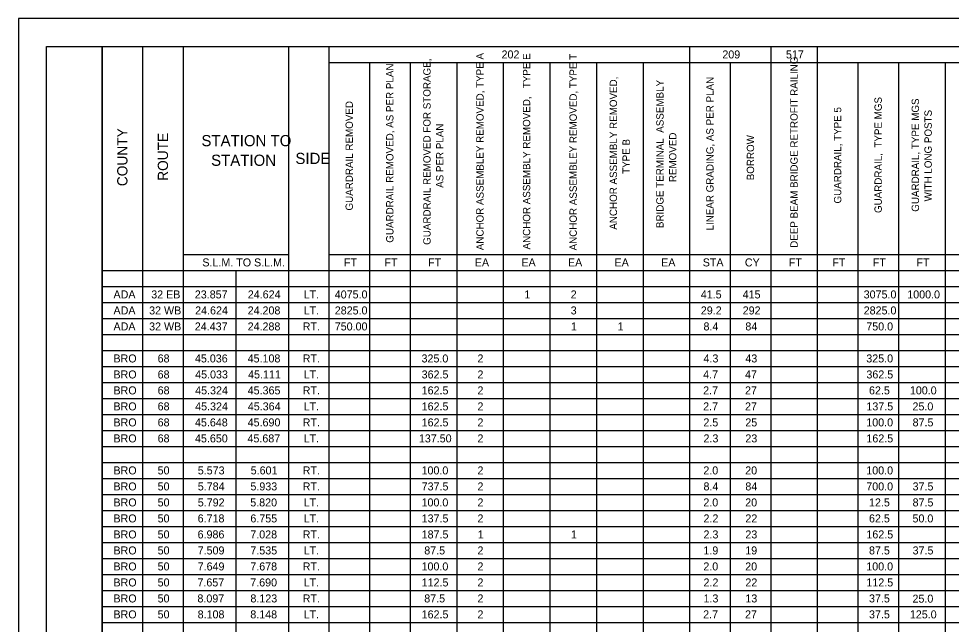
# Model space of a CAD drawing. Extents: x 0 to 34, y 0 to 22.
# Drawn here: x 0 to 16.78, y 11.1 to 22 of the extents above; entities that cross this region are included whole.
import ezdxf

# ---------------------------------------------------------------- set-up
doc = ezdxf.new("R2010")
doc.units = 0
for name, color, linetype in [('Default', 7, 'Continuous'), ('SH_Border', 7, 'Continuous'), ('SH_Cut_Line', 7, 'Continuous')]:
    doc.layers.add(name, color=color, linetype=linetype)

msp = doc.modelspace()

# ---------------------------------------------------------------- linework, layer by layer
at = {"layer": 'Default'}
for p, q in [((1.5, 21.5), (24.449, 21.5)), ((1.5, 21.5), (1.5, 0.498)), ((2.229, 21.5), (2.229, 1.345)), ((2.959, 21.5), (2.959, 1.345)), ((4.852, 21.5), (4.852, 1.345)), ((5.582, 21.5), (5.582, 0.498)), ((12.069, 21.5), (12.069, 0.498)), ((13.528, 21.5), (13.528, 0.498)), ((14.366, 21.5), (14.366, 0.498)), ((5.582, 21.212), (24.428, 21.212)), ((6.311, 21.212), (6.311, 0.498)), ((7.041, 21.212), (7.041, 0.498)), ((7.879, 21.212), (7.879, 0.498)), ((8.717, 21.212), (8.717, 0.498)), ((9.555, 21.212), (9.555, 0.498)), ((10.393, 21.212), (10.393, 0.498)), ((11.231, 21.212), (11.231, 0.498)), ((12.799, 21.212), (12.799, 0.498)), ((15.096, 21.212), (15.096, 0.498)), ((15.825, 21.212), (15.825, 0.498)), ((16.663, 21.212), (16.663, 0.498)), ((2.959, 17.757), (4.852, 17.757)), ((5.582, 17.757), (24.428, 17.757)), ((1.5, 17.469), (24.428, 17.469)), ((3.906, 17.469), (3.906, 1.345)), ((1.5, 17.181), (24.428, 17.181)), ((1.5, 16.893), (24.428, 16.893)), ((1.5, 16.605), (24.428, 16.605)), ((1.5, 16.317), (24.428, 16.317)), ((1.5, 16.029), (24.428, 16.029)), ((1.5, 15.741), (24.428, 15.741)), ((1.5, 15.453), (24.428, 15.453)), ((1.5, 15.166), (24.428, 15.166)), ((1.5, 14.878), (24.428, 14.878)), ((1.5, 14.59), (24.428, 14.59)), ((1.5, 14.302), (24.428, 14.302)), ((1.5, 14.014), (24.428, 14.014)), ((1.5, 13.726), (24.428, 13.726)), ((1.5, 13.438), (24.428, 13.438)), ((1.5, 13.15), (24.428, 13.15)), ((1.5, 12.862), (24.428, 12.862)), ((1.5, 12.574), (24.428, 12.574)), ((1.5, 12.286), (24.428, 12.286)), ((1.5, 11.998), (24.428, 11.998)), ((1.5, 11.71), (24.428, 11.71)), ((1.5, 11.422), (24.428, 11.422)), ((1.5, 11.135), (24.428, 11.135))]:
    msp.add_line(p, q, dxfattribs=at)
at = {"layer": 'SH_Border'}
for points in [[(0.5, 21.5), (1.5, 21.5), (1.5, 0.5), (0.5, 0.5)], [(1.5, 21.5), (33.5, 21.5), (33.5, 0.5), (1.5, 0.5)]]:
    msp.add_lwpolyline(points, close=True, dxfattribs=at)
at = {"layer": 'SH_Cut_Line'}
msp.add_lwpolyline([(0, 0), (34, 0), (34, 22), (0, 22)], close=True, dxfattribs=at)

# ---------------------------------------------------------------- texts
at = {"layer": 'Default'}
for s, height, p in [('ANCHOR ASSEMBLEY REMOVED, TYPE A', 0.13192, (8.364, 17.833)), ('ANCHOR ASSEMBLY REMOVED,   TYPE E', 0.13192, (9.202, 17.846)), ('ANCHOR ASSEMBLEY REMOVED, TYPE T', 0.13192, (10.04, 17.829)), ('GUARDRAIL REMOVED, AS PER PLAN', 0.13192, (6.742, 17.967)), ('GUARDRAIL REMOVED FOR STORAGE,  ', 0.13192, (7.41, 17.929)), ('DEEP BEAM BRIDGE RETROFIT RAILING', 0.13192, (14.013, 17.876)), ('ANCHOR ASSEMBLY REMOVED,          ', 0.13192, (10.763, 18.202)), ('BRIDGE TERMINAL  ASSEMBLY ', 0.13192, (11.601, 18.231)), ('LINEAR GRADING, AS PER PLAN', 0.13192, (12.5, 18.188)), ('GUARDRAIL REMOVED', 0.13192, (6.012, 18.547)), ('GUARDRAIL,  TYPE MGS', 0.13192, (15.526, 18.502)), ('GUARDRAIL, TYPE MGS ', 0.13192, (16.195, 18.525)), ('GUARDRAIL, TYPE 5', 0.13192, (14.797, 18.673)), ('WITH LONG POSTS', 0.13192, (16.425, 18.711)), ('COUNTY', 0.1847, (1.957, 18.985)), ('AS PER PLAN', 0.13192, (7.641, 18.955)), ('ROUTE', 0.1847, (2.687, 19.081)), ('TYPE B', 0.1319, (10.993, 19.207)), ('REMOVED', 0.1319, (11.831, 19.058)), ('BORROW', 0.1319, (13.229, 19.091))]:
    msp.add_text(s, height=height, rotation=90, dxfattribs=at).set_placement(p)
for s, height, p in [('202', 0.144, (8.686, 21.284)), ('209', 0.144, (12.658, 21.284)), ('517', 0.144, (13.802, 21.284)), ('STATION TO ', 0.20155, (3.288, 19.704)), ('STATION', 0.2016, (3.462, 19.351)), ('SIDE', 0.2016, (4.978, 19.384)), ('S.L.M. TO S.L.M.', 0.14396, (3.304, 17.541)), ('FT', 0.144, (5.851, 17.541)), ('FT', 0.144, (6.581, 17.541)), ('FT', 0.144, (7.365, 17.541)), ('EA', 0.144, (8.205, 17.541)), ('EA', 0.144, (9.043, 17.541)), ('EA', 0.144, (9.881, 17.541)), ('EA', 0.144, (10.719, 17.541)), ('EA', 0.144, (11.557, 17.541)), ('STA', 0.144, (12.305, 17.541)), ('CY', 0.144, (13.063, 17.541)), ('FT', 0.144, (13.852, 17.541)), ('FT', 0.144, (14.636, 17.541)), ('FT', 0.144, (15.365, 17.541)), ('FT', 0.144, (16.149, 17.541)), ('ADA', 0.144, (1.706, 16.965)), ('32 EB', 0.144, (2.385, 16.965)), ('23.857', 0.144, (3.169, 16.965)), ('24.624', 0.144, (4.122, 16.965)), ('LT.', 0.144, (5.126, 16.965)), ('4075.0', 0.144, (5.686, 16.965)), ('1', 0.144, (9.097, 16.965)), ('2', 0.144, (9.93, 16.965)), ('41.5', 0.144, (12.27, 16.965)), ('415', 0.144, (13.023, 16.965)), ('3075.0', 0.144, (15.2, 16.965)), ('1000.0', 0.144, (15.984, 16.965)), ('ADA', 0.144, (1.706, 16.677)), ('32 WB', 0.144, (2.347, 16.677)), ('24.624', 0.144, (3.175, 16.677)), ('24.208', 0.144, (4.119, 16.677)), ('LT.', 0.144, (5.126, 16.677)), ('2825.0', 0.144, (5.686, 16.677)), ('3', 0.144, (9.93, 16.677)), ('29.2', 0.144, (12.271, 16.677)), ('292', 0.144, (13.024, 16.677)), ('2825.0', 0.144, (15.2, 16.677)), ('ADA', 0.144, (1.706, 16.389)), ('32 WB', 0.144, (2.347, 16.389)), ('24.437', 0.144, (3.169, 16.389)), ('24.288', 0.144, (4.119, 16.389)), ('RT.', 0.144, (5.109, 16.389)), ('750.00', 0.144, (5.686, 16.389)), ('1', 0.144, (9.935, 16.389)), ('1', 0.144, (10.773, 16.389)), ('8.4', 0.144, (12.319, 16.389)), ('84', 0.144, (13.072, 16.389)), ('750.0', 0.144, (15.247, 16.389)), ('BRO', 0.144, (1.705, 15.813)), ('68', 0.144, (2.5, 15.813)), ('45.036', 0.144, (3.171, 15.813)), ('45.108', 0.144, (4.119, 15.813)), ('RT.', 0.144, (5.109, 15.813)), ('325.0', 0.144, (7.247, 15.813)), ('2', 0.144, (8.253, 15.813)), ('4.3', 0.144, (12.319, 15.813)), ('43', 0.144, (13.072, 15.813)), ('325.0', 0.144, (15.247, 15.813)), ('BRO', 0.144, (1.705, 15.525)), ('68', 0.144, (2.5, 15.525)), ('45.033', 0.144, (3.175, 15.525)), ('45.111', 0.144, (4.127, 15.525)), ('LT.', 0.144, (5.126, 15.525)), ('362.5', 0.144, (7.249, 15.525)), ('2', 0.144, (8.253, 15.525)), ('4.7', 0.144, (12.313, 15.525)), ('47', 0.144, (13.066, 15.525)), ('362.5', 0.144, (15.249, 15.525)), ('BRO', 0.144, (1.705, 15.238)), ('68', 0.144, (2.5, 15.238)), ('45.324', 0.144, (3.175, 15.238)), ('45.365', 0.144, (4.12, 15.238)), ('RT.', 0.144, (5.109, 15.238)), ('162.5', 0.144, (7.249, 15.238)), ('2', 0.144, (8.253, 15.238)), ('2.7', 0.144, (12.313, 15.238)), ('27', 0.144, (13.066, 15.238)), ('62.5', 0.144, (15.296, 15.238)), ('100.0', 0.144, (16.031, 15.238)), ('BRO', 0.144, (1.705, 14.95)), ('68', 0.144, (2.5, 14.95)), ('45.324', 0.144, (3.175, 14.95)), ('45.364', 0.144, (4.122, 14.95)), ('LT.', 0.144, (5.126, 14.95)), ('162.5', 0.144, (7.249, 14.95)), ('2', 0.144, (8.253, 14.95)), ('2.7', 0.144, (12.313, 14.95)), ('27', 0.144, (13.066, 14.95)), ('137.5', 0.144, (15.249, 14.95)), ('25.0', 0.144, (16.078, 14.95)), ('BRO', 0.144, (1.705, 14.662)), ('68', 0.144, (2.5, 14.662)), ('45.648', 0.144, (3.172, 14.662)), ('45.690', 0.144, (4.119, 14.662)), ('RT.', 0.144, (5.109, 14.662)), ('162.5', 0.144, (7.249, 14.662)), ('2', 0.144, (8.253, 14.662)), ('2.5', 0.144, (12.317, 14.662)), ('25', 0.144, (13.071, 14.662)), ('100.0', 0.144, (15.247, 14.662)), ('87.5', 0.144, (16.08, 14.662)), ('BRO', 0.144, (1.705, 14.374)), ('68', 0.144, (2.5, 14.374)), ('45.650', 0.144, (3.172, 14.374)), ('45.687', 0.144, (4.116, 14.374)), ('LT.', 0.144, (5.126, 14.374)), ('137.50', 0.144, (7.199, 14.374)), ('2', 0.144, (8.253, 14.374)), ('2.3', 0.144, (12.319, 14.374)), ('23', 0.144, (13.072, 14.374)), ('162.5', 0.144, (15.249, 14.374)), ('BRO', 0.144, (1.705, 13.798)), ('50', 0.144, (2.5, 13.798)), ('5.573', 0.144, (3.222, 13.798)), ('5.601', 0.144, (4.174, 13.798)), ('RT.', 0.144, (5.109, 13.798)), ('100.0', 0.144, (7.247, 13.798)), ('2', 0.144, (8.253, 13.798)), ('2.0', 0.144, (12.316, 13.798)), ('20', 0.144, (13.069, 13.798)), ('100.0', 0.144, (15.247, 13.798)), ('BRO', 0.144, (1.705, 13.51)), ('50', 0.144, (2.5, 13.51)), ('5.784', 0.144, (3.222, 13.51)), ('5.933', 0.144, (4.169, 13.51)), ('RT.', 0.144, (5.109, 13.51)), ('737.5', 0.144, (7.249, 13.51)), ('2', 0.144, (8.253, 13.51)), ('8.4', 0.144, (12.319, 13.51)), ('84', 0.144, (13.072, 13.51)), ('700.0', 0.144, (15.247, 13.51)), ('37.5', 0.144, (16.08, 13.51)), ('BRO', 0.144, (1.705, 13.222)), ('50', 0.144, (2.5, 13.222)), ('5.792', 0.144, (3.222, 13.222)), ('5.820', 0.144, (4.166, 13.222)), ('LT.', 0.144, (5.126, 13.222)), ('100.0', 0.144, (7.247, 13.222)), ('2', 0.144, (8.253, 13.222)), ('2.0', 0.144, (12.316, 13.222)), ('20', 0.144, (13.069, 13.222)), ('12.5', 0.144, (15.296, 13.222)), ('87.5', 0.144, (16.08, 13.222)), ('BRO', 0.144, (1.705, 12.934)), ('50', 0.144, (2.5, 12.934)), ('6.718', 0.144, (3.22, 12.934)), ('6.755', 0.144, (4.168, 12.934)), ('LT.', 0.144, (5.126, 12.934)), ('137.5', 0.144, (7.249, 12.934)), ('2', 0.144, (8.253, 12.934)), ('2.2', 0.144, (12.319, 12.934)), ('22', 0.144, (13.072, 12.934)), ('62.5', 0.144, (15.296, 12.934)), ('50.0', 0.144, (16.078, 12.934)), ('BRO', 0.144, (1.705, 12.646)), ('50', 0.144, (2.5, 12.646)), ('6.986', 0.144, (3.219, 12.646)), ('7.028', 0.144, (4.167, 12.646)), ('RT.', 0.144, (5.109, 12.646)), ('187.5', 0.144, (7.249, 12.646)), ('1', 0.144, (8.259, 12.646)), ('1', 0.144, (9.935, 12.646)), ('2.3', 0.144, (12.319, 12.646)), ('23', 0.144, (13.072, 12.646)), ('162.5', 0.144, (15.249, 12.646)), ('BRO', 0.144, (1.705, 12.358)), ('50', 0.144, (2.5, 12.358)), ('7.509', 0.144, (3.22, 12.358)), ('7.535', 0.144, (4.168, 12.358)), ('LT.', 0.144, (5.126, 12.358)), ('87.5', 0.144, (7.296, 12.358)), ('2', 0.144, (8.253, 12.358)), ('1.9', 0.144, (12.317, 12.358)), ('19', 0.144, (13.07, 12.358)), ('87.5', 0.144, (15.296, 12.358)), ('37.5', 0.144, (16.08, 12.358)), ('BRO', 0.144, (1.705, 12.07)), ('50', 0.144, (2.5, 12.07)), ('7.649', 0.144, (3.22, 12.07)), ('7.678', 0.144, (4.167, 12.07)), ('RT.', 0.144, (5.109, 12.07)), ('100.0', 0.144, (7.247, 12.07)), ('2', 0.144, (8.253, 12.07)), ('2.0', 0.144, (12.316, 12.07)), ('20', 0.144, (13.069, 12.07)), ('100.0', 0.144, (15.247, 12.07)), ('BRO', 0.144, (1.705, 11.782)), ('50', 0.144, (2.5, 11.782)), ('7.657', 0.144, (3.216, 11.782)), ('7.690', 0.144, (4.166, 11.782)), ('LT.', 0.144, (5.126, 11.782)), ('112.5', 0.144, (7.249, 11.782)), ('2', 0.144, (8.253, 11.782)), ('2.2', 0.144, (12.319, 11.782)), ('22', 0.144, (13.072, 11.782)), ('112.5', 0.144, (15.249, 11.782)), ('BRO', 0.144, (1.705, 11.494)), ('50', 0.144, (2.5, 11.494)), ('8.097', 0.144, (3.216, 11.494)), ('8.123', 0.144, (4.169, 11.494)), ('RT.', 0.144, (5.109, 11.494)), ('87.5', 0.144, (7.296, 11.494)), ('2', 0.144, (8.253, 11.494)), ('1.3', 0.144, (12.319, 11.494)), ('13', 0.144, (13.072, 11.494)), ('37.5', 0.144, (15.296, 11.494)), ('25.0', 0.144, (16.078, 11.49)), ('BRO', 0.144, (1.705, 11.207)), ('50', 0.144, (2.5, 11.207)), ('8.108', 0.144, (3.22, 11.207)), ('8.148', 0.144, (4.167, 11.207)), ('LT.', 0.144, (5.126, 11.207)), ('162.5', 0.144, (7.249, 11.207)), ('2', 0.144, (8.253, 11.207)), ('2.7', 0.144, (12.313, 11.207)), ('27', 0.144, (13.066, 11.207)), ('37.5', 0.144, (15.296, 11.207)), ('125.0', 0.144, (16.031, 11.207))]:
    msp.add_text(s, height=height, dxfattribs=at).set_placement(p)

doc.saveas('drawing.dxf')
